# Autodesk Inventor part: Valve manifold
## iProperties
Created: 2008-09
Part Number: Valve manifold
Document SubType Name: Modeling
Designer: the-dude
Density: 1 g/cm^3
Author: the-dude
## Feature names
1. Housing outline [Revolution]
2. Vent port (lateral) [Revolution]
3. Solenoid port (lateral) [Revolution]
4. Solenoid input port [Revolution]
5. Solenoid input threads 10-32
6. Test adapter port [Mirror]
7. Piston vent port [Revolution]
8. Solenoid output port [Revolution]
